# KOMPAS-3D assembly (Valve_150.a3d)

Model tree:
1. Plane XY
2. Plane ZX
3. Plane ZY
4. X Axis
5. Y Axis
6. Z Axis
7. Origin
8. Control point:1
9. Attachment Point:1
10. Attachment Point:2

Referenced files in C:\Program Files\ASCON\KOMPAS-3D V10\Libs\Piping\Models\Tanks\: Piping_Valve_150_1000.m3d, Piping_Joint_150_1000.m3d, Piping_Flange_150_1000.m3d
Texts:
  Valve Dn 150
  Steel ASTM A295
  Three Point Plane
  Plane at Angle
  Line and Point Plane
  Axis through Two Vertices
  Axis of Feature
  Axis of Conical Surface
  Axis through Edge
  Trim by Surface
  Trim by Sketch
  Intersection Axis of Two Planes
  Two Line Plane
  Line and Face Plane
  Pattern by Sample
  Point in CM
  Feature with No History
  Linear Dimension from Line to Point
  Surface Finish Symbol
  Geometric Tolerance Symbol
  Текст на чертеже
  Линия-выноска #1
  Линия-выноска #2
  Линия-выноска #3
  Отклонения формы и база
  Марка координационной оси
  Марка/позиционное обозначение с линией-выноской
  Марка/позиционное обозначение на линии
  Марка/позиционное обозначение без линии-выноски
  Задвижка Dy 150
  Прокладка Dy 150
  Фланец Dy 150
